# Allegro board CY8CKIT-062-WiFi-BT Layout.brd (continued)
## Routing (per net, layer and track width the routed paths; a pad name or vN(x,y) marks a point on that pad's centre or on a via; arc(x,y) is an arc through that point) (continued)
P8_1: length 24.6
  TOP w0.203: U1.H12 v2(82.2,36.95) ; R61.2 v1(90.53,19.15)
  L06_SIG w0.203: v1(90.53,19.15) 87.22,22.45 87.22,29.3 82.78,33.75 82.78,36.37 v2(82.2,36.95)
  BOTTOM w0.203: R61.2 v1(90.53,19.15)
P8_2: length 23.4
  TOP w0.203: U1.H11 v2(82.2,37.6) ; R60.2 v1(90.53,21.06)
  L06_SIG w0.114: v2(82.2,37.6) 83.21,36.59 83.21,35.28
  L06_SIG w0.203: v1(90.53,21.06) 87.99,23.59 87.99,29.52 83.21,34.31 83.21,35.28
  BOTTOM w0.203: R60.2 v1(90.53,21.06)
P8_3: length 18.4
  TOP w0.203: v2(84.16,35.69) 83.68,35.69 83.13,36.24 U1.G13 ; R53.2 90.62,26.77 v1(90.53,26.87)
  L06_SIG w0.203: v2(84.16,35.69) 84.3,35.55 88.27,35.55 90.13,33.69 90.13,27.26 v1(90.53,26.87)
  BOTTOM w0.203: R53.2 90.75,26.77 90.65,26.87 v1(90.53,26.87)
P8_4: length 17.3
  TOP w0.203: R52.2 v1(90.99,28.68) ; U1.G12 v2(83.42,36.95)
  L06_SIG w0.114: 84.4,36.68 84.4,37.06 84.39,37.06 84.39,37.09 84.2,37.28 83.74,37.28 v2(83.42,36.95)
  L06_SIG w0.203: v1(90.99,28.68) 90.84,28.83 90.84,34.22 89.08,35.98 84.81,35.98 84.4,36.4 84.4,36.68
  BOTTOM w0.203: R52.2 v1(90.99,28.68)
P8_5: length 16.6
  TOP w0.203: v1(91.68,31.63) 92.01,31.29 R47.2 ; U1.G11 v2(83.42,37.6)
  L06_SIG w0.114: v2(83.42,37.6) 84.22,37.6 84.55,37.28 84.94,37.28 85.05,37.17 85.05,36.66 85.06,36.64
  L06_SIG w0.203: 85.06,36.64 85.14,36.57 90.6,36.57 92.36,34.81 92.36,32.31 v1(91.68,31.63)
  BOTTOM w0.203: v1(91.68,31.63) 91.68,30.92 R47.2
P8_6: length 19.4
  TOP w0.203: U1.F13 83.78,36.29 v2(83.92,36.15) ; v1(90.53,24.83) 90.56,24.87 R58.2
  L06_SIG w0.114: 84.73,35.13 84.26,35.13 83.83,35.56 83.83,36.06 v2(83.92,36.15)
  L06_SIG w0.203: v1(90.53,24.83) 89.42,25.94 89.42,33 87.29,35.13 84.73,35.13
  BOTTOM w0.203: R58.2 90.56,24.87 v1(90.53,24.83)
P8_7: length 21.2
  TOP w0.203: v1(90.53,23.06) 90.62,22.96 R59.2 ; U1.F12 v2(84.07,36.95)
  L06_SIG w0.114: v2(84.07,36.95) 83.6,36.48 83.6,35.15 84.21,34.54
  L06_SIG w0.203: 84.21,34.54 85.5,34.54 88.7,31.33 88.7,24.88 v1(90.53,23.06)
  BOTTOM w0.203: v1(90.53,23.06) 90.56,23.06 90.65,22.96 R59.2
P9_0: length 47.7
  TOP w0.114: U1.E11 v2(84.72,37.6)
  L06_SIG w0.114: v1(51.54,21.4) 52.72,22.59 59.99,22.59 60.15,22.76 66.19,22.76 v1(67.03,21.91)
  BOTTOM w0.114: J2.2 50.24,20.11 v1(51.54,21.4) ; v2(84.72,37.6) 84.39,37.28 83.29,37.28 81.79,35.78 81.79,33.06 77.83,29.1 77.83,24.99 74.75,21.91 v1(67.03,21.91)
P9_1: length 44.8
  TOP w0.114: U1.E12 v2(84.72,36.95)
  L06_SIG w0.114: v1(65.53,21.96) 64.92,21.35 61.82,21.35 61.65,21.53 53.57,21.53 v1(53.31,21.28)
  BOTTOM w0.114: v2(84.72,36.95) 84.4,36.63 83.95,36.63 83.24,35.92 83.24,34.96 82.3,34.01 82.3,32.91 78.21,28.82 78.21,24.83 74.65,21.28 66.22,21.28 v1(65.53,21.96) ; v1(53.31,21.28) 52.81,20.77 52.81,19.3 J2.4
P9_2: length 44
  TOP w0.114: v1(81.49,23.04) 81.31,23.23 81.31,31.29 84.53,34.51 84.53,36.49 U1.E13
  L06_SIG w0.114: v1(58.39,23.06) 67.03,23.06 67.54,22.55 76.78,22.55 77.32,23.08 81.45,23.08 v1(81.49,23.04)
  BOTTOM w0.114: J2.6 55.32,20.74 57.63,23.06 v1(58.39,23.06)
P9_3: length 35.4
  TOP w0.114: U1.F11 v2(83.78,38.25)
  L03_SIG w0.114: v1(61.19,24.83) 61.06,24.96 61.06,29.96 62.53,31.44 63.17,31.44 v1(63.22,31.49)
  L06_SIG w0.114: v2(83.78,38.25) 82.85,38.25 82.61,38 82.05,38 81.87,37.82 81.87,36.76 80.48,35.36 78.93,35.36 78.11,34.54 66.27,34.54 v1(63.22,31.49)
  BOTTOM w0.114: v1(61.19,24.83) 61.08,24.72 R161.1 R162.1
P9_4: length 38.6
  TOP w0.114: v1(81.36,21.91) 82,22.55 82,23.96 81.61,24.34 81.61,31.19 85.08,34.67 U1.D13
  L06_SIG w0.114: J2.10 62.1,20.97 80.42,20.97 v1(81.36,21.91)
P9_5: length 35.7
  TOP w0.114: U1.D12 v2(85.37,36.95)
  BOTTOM w0.114: J2.12 64.22,18 74.04,18 74.73,18.69 74.73,20.08 79.1,24.45 79.1,28.59 83.55,33.05 83.55,34.01 85.37,35.83 v2(85.37,36.95)
P9_6: length 29
  TOP w0.114: U1.D11 v2(85.37,37.6)
  BOTTOM w0.114: v2(85.37,37.6) 85.04,37.28 85.04,36.08 82.98,34.01 82.98,33.04 78.6,28.66 78.6,24.6 74.78,20.77 69.51,20.77 J2.16
P9_7: length 29.5
  TOP w0.114: v1(81.41,20.62) 82.25,21.46 82.25,24.24 81.86,24.63 81.86,31.04 85.73,34.91 U1.C13
  L06_SIG w0.114: v1(81.41,20.62) 81.28,20.49 71.77,20.49 J2.18
P10_0: length 53.2
  TOP w0.114: U1.C12 v2(86.02,36.95)
  L06_SIG w0.114: J2.1 52.55,14.43 69.18,14.43 70.21,13.4 71.75,13.4 v1(72.26,13.91)
  BOTTOM w0.114: v1(72.26,13.91) 73.03,14.67 73.84,14.67 75.39,16.22 75.39,19.47 79.86,23.94 79.86,28.24 84.87,33.25 84.87,34.01 86.02,35.16 v2(86.02,36.95)
P10_1: length 54.7
  TOP w0.114: U1.A11 87.33,37.89 v2(87.66,38.21)
  L03_SIG w0.114: v1(79.04,15.11) 80.19,16.25 80.19,29.13 87.66,36.6 v2(87.66,38.21)
  L06_SIG w0.114: J2.3 54.79,14.73 76.97,14.73 77.34,15.11 v1(79.04,15.11)
P10_2: length 50.2
  TOP w0.114: U1.B11 v2(86.67,37.6) ; J2.5 57.49,14.57 68.78,14.57 70.33,13.02 72.69,13.02 v1(73.53,13.86)
  BOTTOM w0.114: v1(73.53,13.86) 74.37,13.86 75.72,15.21 75.72,19.17 80.24,23.69 80.24,28.01 85.28,33.05 85.28,34.01 86.35,35.08 86.35,37.28 v2(86.67,37.6)
P10_3: length 45.3
  TOP w0.114: v1(70.56,13.94) 69.8,13.94 68.78,14.95 59.65,14.95 J2.7 ; U1.C11 v2(86.02,37.6)
  BOTTOM w0.114: v1(70.56,13.94) 71.68,15.05 73.38,15.05 75.01,16.68 75.01,19.7 79.48,24.17 79.48,28.41 84.19,33.13 84.19,34.01 85.69,35.51 85.69,37.28 v2(86.02,37.6)
P10_4: length 52.9
  TOP w0.114: U1.A10 87.18,38.68 87.98,38.68 88.27,38.39 v2(88.27,37.61)
  L03_SIG w0.114: v1(78.99,13.35) 80.47,14.83 80.47,29.01 88.27,36.81 v2(88.27,37.61)
  L06_SIG w0.114: v1(78.99,13.35) 79.53,13.89 79.53,15.44 79.17,15.79 76.43,15.79 75.73,15.09 62.05,15.09 J2.9
P10_5: length 45.1
  TOP w0.114: U1.B10 v2(86.67,38.25)
  BOTTOM w0.114: J2.11 64.63,15.05 67.36,15.05 69.52,12.9 75.6,12.9 77.47,14.77 77.47,19.78 81.08,23.39 81.08,27.73 86.06,32.71 86.06,33.49 87.22,34.66 87.22,37.83 86.8,38.25 v2(86.67,38.25)
P10_6: length 42.2
  TOP w0.114: U1.C10 v2(86.02,38.25)
  BOTTOM w0.114: J2.13 66.78,15.44 67.79,15.44 69.95,13.28 75.44,13.28 77.14,14.98 77.14,20.03 80.62,23.51 80.62,27.83 85.67,32.89 85.67,33.7 86.99,35.02 86.99,37.74 86.8,37.93 86.34,37.93 v2(86.02,38.25)
P10_7: length 63.2
  TOP w0.114: v1(88.94,38.74) 88.49,39.19 U1.A9
  L03_SIG w0.114: v1(94.31,66.6) 95.52,66.6 98.6,63.52 98.6,58.41 95.17,54.98 95.17,48.07 92.99,45.88 92.99,44.83 89.61,41.49 88.95,40.84 88.94,40.78 88.94,40.65 88.94,40.65 v1(88.94,38.74)
  L06_SIG w0.114: v1(94.31,66.6) 94.04,66.87 86.84,66.87 85.07,68.65 84.94,68.65 84.93,68.65 81.41,68.65 78.19,65.43 74.55,65.43 73.74,66.24 71.8,66.24 J21.5
P11_0: length 32.1
  TOP w0.114: U1.B9 v2(86.67,38.9)
  L03_SIG w0.114: v1(79.04,17.72) 79.65,18.33 79.65,29.41 86.35,36.1 86.35,38.58 v2(86.67,38.9)
  BOTTOM w0.114: R175.1 84.05,16.83 83.03,17.85 81.89,17.85 81.37,17.33 R173.1 79.44,17.33 v1(79.04,17.72)
P11_1: length 40.4
  TOP w0.114: v1(118.97,44.04) 118.97,45.83 118.58,46.22 R19.2 ; U1.C9 v2(86.02,38.9)
  L06_SIG w0.114: v1(118.97,44.04) 118.15,43.21 118.15,41.92 114.78,38.55 93.32,38.55 92.65,37.88 88.76,37.88 88.06,38.58 86.34,38.58 v2(86.02,38.9)
P11_2: length 32.8
  TOP w0.114: v2(88,39.97) 87.87,39.84 U1.A8
  L03_SIG w0.114: v2(88,39.97) 87.07,39.04 87.07,36.42 79.91,29.26 79.91,17.34 v1(78.97,16.4)
  BOTTOM w0.114: R176.1 82.27,13.54 R177.1 80.48,15.32 79.4,16.4 v1(78.97,16.4)
P11_3: length 34.6
  TOP w0.114: v1(105.23,41.37) 105.23,47.6 R17.1 ; U1.B8 v2(86.67,39.55) ; U4.D4 112.34,42.14 v1(111.2,42.14)
  L06_SIG w0.114: v1(105.23,41.37) 104.45,40.58 90.53,40.58 89.5,39.55 v2(86.67,39.55)
  BOTTOM w0.114: v1(111.2,42.14) 108.54,42.14 108,41.6 107.15,41.6 106.77,41.98 105.84,41.98 v1(105.23,41.37)
P11_4: length 34.4
  TOP w0.114: U5.3 106.5,39.96 v1(106.49,39.97) 106.01,40.45 102.59,40.45 R38.1 ; U1.C8 v2(86.02,39.55) ; U4.C4 112.36,40.11 v1(111.02,40.11)
  L06_SIG w0.114: v1(106.49,39.97) 105.53,39.01 89.83,39.01 89.61,39.23 86.34,39.23 v2(86.02,39.55)
  BOTTOM w0.114: v1(106.49,39.97) 106.63,40.11 v1(111.02,40.11)
P11_5: length 32.3
  TOP w0.114: v1(94.34,39.95) 93.79,40.49 U1.A7 ; 105.23,38.31 v1(105.23,39.82) ; U4.D2 v1(115.26,42.01)
  L06_SIG w0.114: v1(115.26,42.01) 114.48,41.22 110.08,41.22 109.5,41.8 107.97,41.8 107.96,41.8 107.58,41.8 107.58,41.8 107.56,41.8 105.86,40.1 105.51,40.1 v1(105.23,39.82) 104.8,39.39 94.89,39.39 v1(94.34,39.95)
P11_6: length 32.6
  TOP w0.114: U5.5 v1(107.77,42.26) ; U1.B7 v2(86.67,40.2) ; U4.D3 v1(113.48,42.01)
  L06_SIG w0.114: v1(107.77,42.26) 104.65,42.26 103.74,41.35 89.92,41.35 89.25,40.68 87.68,40.68 87.2,40.2 v2(86.67,40.2)
  BOTTOM w0.114: v1(113.48,42.01) 112.37,42.01 111.63,42.74 108.25,42.74 v1(107.77,42.26)
P11_7: length 35.6
  TOP w0.114: v1(106.55,41.45) 106.5,41.5 U5.6 ; U4.B2 v1(114.48,40.01) ; U1.C7 v2(86.02,40.2)
  L06_SIG w0.114: v1(106.55,41.45) 105.99,41.45 105.56,41.88 104.83,41.88 103.91,40.97 90.28,40.97 89.61,40.29 87.72,40.29 87.31,39.88 86.34,39.88 v2(86.02,40.2)
  BOTTOM w0.114: v1(106.55,41.45) 107.24,40.76 109.65,40.76 109.86,40.96 113.52,40.96 v1(114.48,40.01)
P12_0: length 180.1
  TOP w0.114: U1.A6 87.53,41.14 v2(88.01,41.62)
  L03_SIG w0.114: J5.4 66.83,43.48 66.83,46.19 65.38,47.64 65.38,55.8 v1(66.65,57.07) ; J3.4 31.84,63.37 30.61,63.37 25.43,58.18 25.43,49.29 23.67,47.54 23.67,30.45 22.78,29.56 22.78,12.06 30.19,4.65 J14.2 ; v1(92.18,61.92) 92.18,61.41 94.6,58.99 94.6,55.93 94.34,55.67 94.34,48.68 92.08,46.42 92.08,45.14 88.56,41.62 v2(88.01,41.62)
  L06_SIG w0.114: J3.4 35.11,63.37 36.86,63.37 38.73,61.49 50.97,61.49 54.91,57.55 61.52,57.55 v1(62.46,58.49) 63.88,57.07 v1(66.65,57.07) 66.65,57.6 68.32,59.28 73.56,59.28 74.93,60.65 78.97,60.65 82.27,63.95 84.43,63.95 85.95,62.43 91.67,62.43 v1(92.18,61.92)
  BOTTOM w0.114: R77.1 v1(62.46,58.49)
P12_1: length 153.8
  TOP w0.114: U1.B6 v2(86.67,40.85)
  L03_SIG w0.114: v1(63.58,53.48) 63.8,53.26 63.8,46.7 62.94,45.84 J5.1 ; J3.5 30.94,64.05 25.04,58.16 25.04,49.32 23.42,47.69 23.42,30.57 22.53,29.68 22.53,11.8 27.65,6.68 J14.3
  L06_SIG w0.114: v1(63.58,53.48) 63.58,54.07 v1(62.59,55.06) 63.09,55.57 63.09,57.35 62.84,57.6 62.08,57.6 61.59,57.12 54.86,57.12 50.74,61.24 34.7,61.24 J3.5
  BOTTOM w0.114: v1(62.59,55.06) 61.58,55.06 R85.1 ; J5.1 61.52,43.26 61.52,39.29 62.43,38.38 64.48,38.38 65.46,37.41 76.68,37.41 77.2,37.93 85.5,37.93 85.69,38.12 85.69,38.39 85.89,38.58 86.8,38.58 87,38.77 87,40.53 v2(86.67,40.85)
P12_2: length 152.3
  TOP w0.114: U1.C6 v2(86.02,40.85)
  L03_SIG w0.114: v1(62.59,56.96) 62,56.96 61.67,56.63 61.67,54.6 63.42,52.85 63.42,46.96 61.8,45.33 61.8,43.28 J5.3 ; J14.4 25.11,8.59 22.28,11.42 22.28,29.89 23.11,30.73 23.11,45 21.41,46.7 21.41,56.08 28.4,63.06 J3.6
  L06_SIG w0.114: v1(62.59,56.96) 62.18,56.56 54.81,56.56 51.54,59.83 33.56,59.83 J3.6
  BOTTOM w0.114: v1(62.59,56.96) 61.58,56.96 R81.1 ; v2(86.02,40.85) 86.34,40.53 86.34,39.42 86.16,39.23 85.89,39.23 85.69,39.04 85.69,39.02 85.26,38.58 77.02,38.58 76.35,37.91 65.55,37.91 64.31,39.16 64.31,40.77 J5.3
P12_3: length 87.9
  TOP w0.114: v1(93.38,63.64) 93.38,60.39 94.62,59.15 94.62,59.13 94.63,59.12 94.63,56.23 94.62,56.22 94.62,56.21 91.41,53.01 91.41,48.46 90.19,47.23 90.19,45.75 87.54,43.1 87.54,42.3 U1.A5
  L06_SIG w0.114: v1(93.38,63.64) 92.66,62.93 86.33,62.93 84.56,64.71 82.02,64.71 78.46,61.16 74.65,61.16 73.56,60.06 65.48,60.06 63.77,61.77 39.24,61.77 J3.3
P12_4: length 69.4
  TOP w0.114: U1.B5 v2(86.67,41.5) ; v1(63.73,58.62) 64.21,58.13 66.67,58.13 69.09,60.55 71.25,60.55 72.35,61.65 76.8,61.65 81.8,66.65 91.62,66.65 v1(92.08,66.19)
  L03_SIG w0.114: v2(86.67,41.5) 87.19,41.5 87.48,41.22 88.51,41.22 92.41,45.11 92.41,46.26 94.64,48.5 94.64,55.29 97.83,58.48 97.83,63.15 95.38,65.6 93.31,65.6 92.72,66.19 v1(92.08,66.19)
  BOTTOM w0.114: R74.1 v1(63.73,58.62) R83.1
P12_5: length 69.4
  TOP w0.114: v1(93.29,66.28) 92.66,66.92 81.68,66.92 76.72,61.96 72.3,61.96 71.2,60.85 68.76,60.85 66.52,58.62 v1(65.38,58.62) ; U1.C5 v2(86.02,41.5)
  L03_SIG w0.114: v2(86.02,41.5) 86.35,41.18 87.06,41.18 87.25,40.99 88.72,40.99 92.71,44.97 92.71,46.09 94.89,48.27 94.89,55.06 98.25,58.41 98.25,63.37 95.57,66.05 93.53,66.05 v1(93.29,66.28)
  BOTTOM w0.114: R82.1 v1(65.38,58.62) R73.1
P12_6: length 5.4
  TOP w0.114: U1.A4 v2(86.75,42.15)
  BOTTOM w0.114: v2(86.75,42.15) 88.52,42.15 89.04,41.63 R131.1 R135.1
P12_7: length 6.3
  TOP w0.114: U1.B4 v2(86.1,42.15)
  BOTTOM w0.114: v2(86.1,42.15) 86.47,42.52 88.37,42.52 89.14,43.28 R126.1 R120.1
P13_0: length 75.5
  TOP w0.114: v2(86.69,44.93) 86.69,44.69 U1.B1
  L03_SIG w0.114: 86.69,46.19 v2(86.69,44.93)
  L03_SIG w0.203: v1(88.49,65.47) 89.28,65.47 89.89,64.86 89.89,61.89 91.18,60.61 91.18,54.68 88.87,52.38 88.87,50.61 87.73,49.47 87.73,47.24 86.69,46.19
  L06_SIG w0.114: v1(88.49,65.47) 87.98,64.96 86.57,64.96 85.12,66.41 81.25,66.41 77.75,62.91 67.28,62.91 66.93,62.55 64.72,62.55 64.36,62.91 43.19,62.91 J3.1
P13_1: length 83
  TOP w0.114: U1.A3 89.81,45.87 89.81,47.36 91.16,48.71 91.16,53.1 94.39,56.33 94.39,59.02 93.09,60.32 93.09,62.81 v1(92.28,63.62)
  L06_SIG w0.114: J3.2 41.54,62.02 64.21,62.02 65.79,60.44 73.55,60.44 74.51,61.41 78.21,61.41 81.89,65.09 84.68,65.09 86.59,63.18 91.84,63.18 v1(92.28,63.62)
P13_2: length 62.8
  TOP w0.114: U1.B3 v2(86.67,43.37)
  L03_SIG w0.114: v2(86.67,43.37) 86.35,43.7 86.35,45.28
  L03_SIG w0.178: v1(89,64.71) 89,62.81
  L03_SIG w0.203: 89,62.81 86.72,60.52 86.72,56.84 86.08,56.2 86.08,53.64 87.58,52.14 87.58,51.29 87.1,50.81 87.1,47.48 86.05,46.42 86.05,45.57 86.33,45.28 86.35,45.28
  L06_SIG w0.203: J21.2 65.49,67.54 66.75,66.28 66.75,64.12 67.16,63.71 77.26,63.71 81.66,68.12 84.81,68.12 86.69,66.24 89.26,66.24 89.64,65.85 89.64,65.35 v1(89,64.71)
  BOTTOM w0.178: R72.2 67.92,62.96 66.77,64.11 66.77,66.25 J21.2
P13_3: length 58.2
  TOP w0.203: U1.B2 v2(86.67,44.02)
  L03_SIG w0.203: v2(86.67,44.02) 87.27,44.63 87.27,45.84 89.49,48.05 89.49,51.99 92.68,55.19 93.09,55.19 94.06,56.15 94.06,58.64 90.65,62.04 v1(90.65,64.71)
  L06_SIG w0.203: v1(70.58,61.65) 71.28,62.36 77.99,62.36 81.44,65.81 84.85,65.81 86.61,64.06 90,64.06 v1(90.65,64.71)
  BOTTOM w0.178: J21.4 68.03,67.54 69.31,66.26 69.31,60.89 69.55,60.65 R71.1 v1(70.58,61.65)
P13_4: length 33.8
  TOP w0.114: U1.C2 v2(86.02,44.02)
  L03_SIG w0.114: v2(86.02,44.02) 86.02,44.2 83.83,46.39 83.83,46.96
  L03_SIG w0.178: v1(80.87,58.41) 81.76,57.52 81.76,56.58 81.38,56.2 81.38,51.63 83.83,49.18 83.83,46.96
  BOTTOM w0.178: v1(80.87,58.41) 80.25,59.03 77.28,59.03 76.94,59.38 74.52,59.38 74.13,59.77 R70.1 74.13,61.55 71.85,63.83 71.85,66.26 70.57,67.54 J21.6
P13_5: length 41.6
  TOP w0.114: U1.C1 v2(86.02,44.67)
  L03_SIG w0.114: v1(86.97,67.51) 87.48,67 87.48,62.68 83.41,58.62 83.41,56.05 84.3,55.16 84.3,52.8 85.57,51.53 85.57,49.57 85.83,49.32 85.83,48.96 85.45,48.58 85.45,45.25 v2(86.02,44.67)
  L06_SIG w0.114: J21.8 73.1,67.55 74.48,68.92 85.55,68.92 v1(86.97,67.51)
P13_6: length 91.1
  TOP w0.114: U1.D3 v2(85.37,43.37)
  L03_SIG w0.114: v1(78.97,18.97) 79.4,19.4 79.4,29.57 85.69,35.86 85.69,39.93 85.12,40.5 85.12,42.65 85.37,42.89 v2(85.37,43.37)
  L06_SIG w0.114: v2(85.37,43.37) 85.69,43.7 86.8,43.7 87.13,43.38 88.6,43.38 89,43.78 100.18,43.78 101.27,44.87 111.78,44.87 113.36,46.46 114.03,46.46 116.41,48.84 119.2,48.84 120.52,47.52 120.52,46.57 120.85,46.24 120.85,45.15 121.11,44.9 123.01,44.9 128.73,39.18 132.61,39.18 132.72,39.08 v1(132.72,39.06) ; J2.19 76.74,16.74 v1(78.97,18.97)
  BOTTOM w0.114: v1(132.72,39.06) 133.1,38.68 R45.2
P13_7: length 88.1
  TOP w0.114: U1.D2 v2(85.37,44.02) ; v1(125.73,42.99) 125.68,43.05 R31.1
  L03_SIG w0.114: v2(85.37,44.02) 85.05,43.7 85.05,43.26 85.04,43.25 85.04,43.1 84.47,42.53 84.47,41.58 84.71,41.34 84.71,38.73 85.04,38.39 85.04,35.63 79.15,29.74 79.15,20.24 v1(78.92,20.01) ; v1(125.32,49.09) 125.2,48.96 125.2,43.53 v1(125.73,42.99)
  L06_SIG w0.114: v1(125.32,49.09) 125.12,49.09 121.43,52.78 116.19,52.78 115.34,51.94 108.74,51.94 107.16,50.36 100.94,50.36 99.8,49.22 v1(96.4,49.22) ; J2.20 73.83,20.01 v1(78.92,20.01)
  BOTTOM w0.114: v1(96.4,49.22) 96.19,49.01 95.14,49.01 93.62,47.49 93.62,46.27 93.27,45.92 89.13,45.92 88.75,46.3 87.99,46.3 87.73,46.04 87.73,44.9 86.99,44.16 86.99,43.89 86.8,43.7 86.79,43.7 86.78,43.7 85.7,43.7 v2(85.37,44.02)
PMIC_EN: length 89.7
  TOP w0.114: v1(96.88,58.74) 96.88,56.43 98.25,55.06 98.25,51.42 v1(99.71,49.95) ; U9.3 64.78,34.42 65.28,34.92 v1(65.43,34.92) ; v1(66.4,27.5) 65.89,27.5 65.44,27.05 U10.3
  L03_SIG w0.114: v1(59.39,46.05) 59.39,41.98 60.03,41.33 60.03,41.08 60.64,40.48 60.64,36.94 61.47,36.11 65.13,36.11 65.48,35.76 65.48,34.97 v1(65.43,34.92) 64.62,34.1 64.62,29.28 v1(66.4,27.5)
  L06_SIG w0.114: v1(66.32,53.84) 68.45,55.97 68.45,58.26 69.09,58.89 73.63,58.89 75.13,60.39 79.1,60.39 82.35,63.65 84.37,63.65 85.85,62.17 91.16,62.17 94.59,58.74 v1(96.88,58.74)
  BOTTOM w0.114: v1(66.32,53.84) 66.32,51.97 60.41,46.05 v1(59.39,46.05) ; SW7.6 99.92,51.12 99.71,50.91 v1(99.71,49.95)
PMOD_SSEL_P12_5: length 103.1
  TOP w0.114: v1(26.46,58.51) 27.84,59.89 48.36,59.89 51.79,56.46 61.06,56.46 61.57,55.95 66.31,55.95 v1(66.35,55.9)
  L03_SIG w0.114: v1(26.46,58.51) 27.08,57.89 27.08,38.85 25.63,37.41 25.63,29.02 25.1,28.49 25.1,23.03 24.79,22.73 24.79,10.96 J14.1
  BOTTOM w0.114: R82.2 65.44,55.87 66.32,55.87 v1(66.35,55.9)
SDIO_CLK: length 5.4
  TOP w0.114: v1(125.12,50.54) 125.37,50.79 U6.20
  BOTTOM w0.114: R108.2 124.94,47.32 124.94,48.6 124.82,48.73 124.82,50.23 v1(125.12,50.54)
SDIO_CMD: length 4.1
  TOP w0.114: v1(126.07,50.06) 126.42,50.4 126.42,51.7 126.07,52.05 U6.22
  BOTTOM w0.114: R99.2 126.73,50.72 v1(126.07,50.06)
SDIO_DATA0: length 8
  TOP w0.114: U6.24 126.27,52.95 127.18,52.04 127.18,52.02 127.18,52.02 127.18,50.81 v1(128.17,49.83)
  BOTTOM w0.114: R110.2 127.82,47.21 127.82,49.48 v1(128.17,49.83)
SDIO_DATA1: length 10.3
  TOP w0.114: v1(130.51,49.62) 129.67,50.46 128.93,50.46 127.96,51.44 127.96,52.17 126.28,53.85 U6.26
  BOTTOM w0.114: v1(130.51,49.62) 130.81,49.32 130.81,47.21 R111.2
SDIO_DATA2: length 7.3
  TOP w0.114: U6.23 126.18,52.5 126.8,51.88 126.8,51.86 126.8,51.86 126.8,50.18 v1(127.11,49.87)
  BOTTOM w0.114: v1(127.11,49.87) 127.11,49.84 126.72,49.45 126.72,48.84 126.57,48.68 126.57,47.45 125.68,46.57 R112.2
SDIO_DATA3: length 9
  TOP w0.114: v1(129.34,49.8) 128.98,49.8 127.56,51.22 127.56,52.09 126.26,53.4 U6.25
  BOTTOM w0.114: R109.2 129.34,47.23 v1(129.34,49.8)
SHIELD: length 60.4
  TOP w0.381: 117.86,11.15 v1(117.86,11.63) ; v1(117.86,11.63) 117.86,12.77 ; v1(117.86,11.63) 117.13,11.63 ; v1(117.86,11.63) 118.33,11.63 ; v1(132.21,16.32) 132.21,17.1 ; v1(132.21,16.32) 132.21,16.16 ; v1(132.21,16.32) 131.11,16.32 ; v1(132.21,16.32) 132.37,16.32 ; 132.64,24.14 v1(132.64,24.66) ; v1(132.64,24.66) 133.23,24.66 ; v1(132.64,24.66) 132.12,24.66 ; v1(132.64,24.66) 132.64,25.93 ; 116.81,2.61 v1(118.52,2.61) ; v1(118.52,2.61) 118.52,2.47 ; v1(118.52,2.61) 118.66,2.61 ; v1(118.52,2.61) 118.52,2.77 ; 113.28,6.57 v1(114.53,6.57) ; v1(114.53,6.57) 114.72,6.57 ; v1(114.53,6.57) 114.53,5.95 ; v1(114.53,6.57) 114.53,6.76 ; v1(99.26,30.19) 99.54,30.19 ; v1(99.26,30.19) 99.26,31.36 ; v1(99.26,30.19) 99.26,29.91 ; v1(99.26,30.19) 98.57,30.19 ; v1(100.66,20.46) 100.66,20.63 ; v1(100.66,20.46) 100.66,20.1 ; v1(100.66,20.46) 100.82,20.46 ; v1(100.66,20.46) 99.16,20.46 ; v1(99.26,2.38) 99.26,3.35 ; v1(99.26,2.38) 99.26,1.89 ; v1(99.26,2.38) 99.75,2.38 ; 101.07,16.48 v1(102.03,16.48) ; v1(102.03,16.48) 102.64,16.48 ; v1(102.03,16.48) 102.03,15.87
  BOTTOM w0.381: 130.93,24.66 v1(132.64,24.66) ; v1(132.64,24.66) 132.64,25.22 ; v1(132.64,24.66) 133.2,24.66 ; v1(132.64,24.66) 132.64,23.59 ; 99.26,1.28 v1(99.26,2.38) ; v1(99.26,2.38) 99.26,3.27 ; v1(99.26,2.38) 100.16,2.38 ; v1(99.26,30.19) 99.26,30.93 ; v1(99.26,30.19) 100,30.19 ; v1(99.26,30.19) 99.26,28.94 ; v1(102.03,16.48) 102.03,17.1 ; v1(102.03,16.48) 102.03,15.12 ; v1(102.03,16.48) 102.66,16.48 ; v1(102.03,16.48) 100.63,16.48 ; 117.18,2.61 v1(118.52,2.61) ; v1(118.52,2.61) 118.52,1.17 ; v1(118.52,2.61) 118.52,3.38 ; v1(118.52,2.61) 119.29,2.61 ; 130.9,16.32 v1(132.21,16.32) ; v1(132.21,16.32) 132.21,17.35 ; v1(132.21,16.32) 133.23,16.32 ; v1(132.21,16.32) 132.21,14.87 ; v1(114.53,6.57) 114.53,7.37 ; v1(114.53,6.57) 114.53,5.48 ; v1(114.53,6.57) 115.33,6.57 ; v1(114.53,6.57) 112.85,6.57 ; 100.66,19.28 v1(100.66,20.46) ; v1(100.66,20.46) 100.66,21.24 ; v1(100.66,20.46) 99.08,20.46 ; v1(100.66,20.46) 101.43,20.46 ; R44.1 R45.1 133.1,34.01 R145.1 133.03,33 133.38,32.66 134.58,32.66 134.85,32.39 134.85,31.36 134.87,31.34 v1(134.81,31.28)
SPI_MISO: length 79.3
  TOP w0.114: v1(45.67,33.11) 45.67,32.61 45.35,32.29 U2.4 ; v1(53.67,54.71) 53.18,54.22 52.25,54.22 50.74,55.73 v1(48.17,55.73)
  L03_SIG w0.114: v1(45.67,33.11) 46.33,33.77 46.33,44.82 47.83,46.33 47.83,52.19 48.17,52.53 v1(48.17,55.73)
  L06_SIG w0.114: J6.9 3.66,28.81 5.68,28.81 6.22,28.26 25.72,28.26 28.11,30.66 34.47,30.66 36.43,32.61 45.17,32.61 v1(45.67,33.11)
  BOTTOM w0.114: v1(53.67,54.71) 53.91,54.95 U17.17
SPI_MOSI: length 86.2
  TOP w0.114: U2.28 39.84,39.91 38.68,41.06 38.68,42.59 37.14,44.14 v1(30.48,44.14) 29.87,43.53 29.87,41.45 26.04,37.61 7.16,37.61 5.77,39.01 3.44,39.01 J6.3 ; v1(32.37,57.1) 34.88,59.61 48.01,59.61 52.24,55.38 53.19,55.38 v1(53.67,55.85)
  L03_SIG w0.114: v1(30.48,44.14) 32.37,46.03 v1(32.37,57.1)
  BOTTOM w0.114: U17.19 53.77,55.95 v1(53.67,55.85)
SPI_SCLK: length 81.5
  TOP w0.114: J6.5 3.43,34.12 17.52,34.12 18.5,35.1 25.35,35.1 26.09,35.83 28.14,35.83 v1(28.57,35.4) ; v1(33.48,35.28) 33.69,35.49 U2.40
  L03_SIG w0.114: v1(31.66,54.72) 31.63,54.72 28.57,51.66 v1(28.57,35.4)
  L06_SIG w0.114: v1(52.53,55.85) 51.84,55.17 43.55,55.17 42.91,55.82 32.75,55.82 v1(31.66,54.72)
  BOTTOM w0.114: v1(28.57,35.4) 29.2,34.77 30.87,34.77 31.38,35.28 v1(33.48,35.28) ; v1(52.53,55.85) 53.09,55.3 53.9,55.3 54.06,55.45 U17.18
SPI_SSEL: length 86
  TOP w0.114: v1(33.48,34.14) 34.43,35.09 U2.41 ; J6.7 3.37,33.86 17.73,33.86 18.69,34.82 25.48,34.82 25.98,35.32 v1(27.43,35.32) ; v1(31.68,55.99) 32.05,55.99 35.31,59.26 47.72,59.26 52.27,54.71 v1(52.53,54.71)
  L03_SIG w0.114: v1(31.68,55.99) 27.76,52.08 27.76,38.14 27.43,37.81 v1(27.43,35.32)
  BOTTOM w0.114: v1(33.48,34.14) 32.9,34.71 31.75,34.71 31.32,34.28 28.85,34.28 27.81,35.32 v1(27.43,35.32) ; U17.16 54.2,54.45 53.9,54.15 53.09,54.15 v1(52.53,54.71)
SWD_RST_L: length 105.6
  TOP w0.114: J12.10 58.45,6.14 58.81,6.5 66.51,6.5 v1(66.85,6.16) 67.16,6.48 78.66,6.48 78.84,6.29 J11.10
  L03_SIG w0.114: v1(33.96,7.92) 33.76,8.12 33.76,15.44 J1.6 ; v1(66.85,6.16) 66.75,6.26 66.75,21.21 66.48,21.49 66.48,22.47 67.56,23.55 67.56,34.94 65.51,37 63.58,37 62.94,37.64 J5.5
  L06_SIG w0.114: J12.10 58.45,5.95 57.62,6.78 41.1,6.78 39.73,5.41 35.46,5.41 33.96,6.91 v1(33.96,7.92)
  BOTTOM w0.114: R182.1 79.44,7.28 78.84,6.68 J11.10 ; J12.10 58.45,6.62 R190.2
TCLK_SWCLK: length 30
  TOP w0.114: v1(75.26,7.51) 75.04,7.29 55.33,7.29 54.64,6.6 J12.4
  BOTTOM w0.114: R191.2 78.22,8.41 76.3,8.41 76.02,8.69 R183.1 75.92,8.17 v1(75.26,7.51) 75.03,7.28 J11.4
TMS_SWDIO: length 29
  TOP w0.114: J12.2 53.37,6.09 54.84,7.56 73.2,7.56 73.38,7.74 v1(74.02,7.74)
  BOTTOM w0.114: J11.2 73.76,6.55 74.02,6.8 v1(74.02,7.74) 72.81,7.74 R194.1 R192.2
TRACECLK: length 3.2
  BOTTOM w0.114: J12.12 59.72,7.08 R189.2
TRACEDATA_0: length 18.9
  L03_SIG w0.114: J12.14 60.99,9.97 61.73,10.72 61.73,21.44 v1(62.2,21.91)
  BOTTOM w0.114: v1(62.2,21.91) 61.95,21.66 R161.2
TRACEDATA_1: length 3.4
  BOTTOM w0.114: R188.2 62.26,6.72 J12.16
TRACEDATA_2: length 3.3
  BOTTOM w0.114: R187.2 63.53,6.97 J12.18
TRACEDATA_3: length 3.5
  BOTTOM w0.114: R186.2 64.8,6.52 J12.20
TS: length 8.8
  L06_SIG w0.114: TP7.1 53.41,50.9 v1(50.26,50.9)
  BOTTOM w0.114: U19.5 46.22,51.62 46.94,50.9 R95.1 R94.2 v1(50.26,50.9)
UART_CTS: length 88.4
  TOP w0.114: U2.61 41.04,29.65 41.15,29.54 41.15,28.36 v1(41.38,28.14)
  L03_SIG w0.114: v1(53.67,53.06) 55.22,51.51 55.22,51.5 55.44,51.29 55.44,46.77 v1(56.69,45.51) ; v1(41.38,28.14) 41.63,28.39 42.01,28.39 42.29,28.67 42.29,39.21 41.55,39.95 41.55,45.64 v1(40.84,46.35)
  L06_SIG w0.114: J6.2 6.03,41.6 7.17,41.6 8.44,40.33 16.41,40.33 18.08,42 20.4,42 20.7,41.7 23.85,41.7 28.5,46.35 v1(40.84,46.35) 41.38,46.88 44.22,46.88 44.91,46.19 56.01,46.19 v1(56.69,45.51)
  BOTTOM w0.114: v1(53.67,53.06) 54.06,53.45 U17.14
UART_RTS: length 83
  TOP w0.114: v1(52.43,53.47) 52.35,53.38 v1(51.33,53.38) ; v1(44.53,38.07) 44.31,38.29 U2.18
  L03_SIG w0.114: v1(44.53,38.07) 44.6,38 44.6,21.7 v1(41.82,18.92)
  L06_SIG w0.114: v1(41.82,18.92) 41.44,18.54 26.07,18.54 23.83,16.31 5.45,16.31 J7.7
  BOTTOM w0.114: v1(44.53,38.07) 45.31,38.85 47.83,38.85 48.72,39.74 48.72,43.68 51.33,46.3 v1(51.33,53.38) ; U17.15 54.24,53.95 54.06,53.77 52.74,53.77 v1(52.43,53.47)
UART_RX: length 72.3
  TOP w0.114: U2.21 42.64,39.99 42.75,40.11 v1(42.8,40.11)
  L03_SIG w0.114: v1(46.27,28.62) 46.25,28.64 46.25,30.93 47.32,32 v1(47.32,39.68)
  L06_SIG w0.114: J6.13 3.4,26.27 6.52,26.27 7.42,25.37 14.4,25.37 15.39,26.36 27.91,26.36 31.22,29.66 37.19,29.66 37.95,30.42 44.47,30.42 v1(46.27,28.62) ; v1(47.32,39.68) 46.82,39.18 43.18,39.18 42.7,39.67 42.7,40.01 v1(42.8,40.11)
  BOTTOM w0.114: J6.13 3.53,26.39 6.62,26.39 R156.1
UART_TX: length 59.7
  TOP w0.114: v1(43.76,40.11) 43.04,39.38 U2.20
  L03_SIG w0.114: v1(43.76,40.11) 43.76,37.76 44.17,37.36 44.17,30.35 43.51,29.69 43.51,26.61 v1(44.02,26.1)
  L06_SIG w0.114: v1(44.02,26.1) 43.11,25.2 33.32,25.2 32.07,26.44 29.67,26.44 28.68,25.44 16.65,25.44 15.71,24.5 8.6,24.5 v1(7.2,23.11)
  BOTTOM w0.114: J6.14 5.82,24.11 R159.1 v1(7.2,23.11)
USB_DEV_VBUS_DET: length 29
  L03_SIG w0.114: v1(77.6,59.81) 77.6,59.48 78.71,58.36 78.71,52.77 77.44,51.5 v1(77.44,49.6)
  BOTTOM w0.114: v1(77.44,49.6) 78.21,50.36 86.33,50.36 87.35,49.34 87.35,46.93 87.46,46.83 R107.1 88.73,46.83 88.91,46.65 U22.4 ; v1(77.6,59.81) 77.6,60.24 77.19,60.65 R70.2
USB_DM: length 18.1
  TOP w0.203: v1(80.43,49.45) 80.14,49.74 80.14,49.76 80.19,49.81 80.19,51.85 80.66,52.32 84.25,52.32 85.09,53.16 85.4,53.16 85.61,52.96 85.61,52.76 85.37,52.52 v1(85.24,52.52) ; U1.L1 v2(80.25,44.67)
  BOTTOM w0.152: 78.33,46.96 78.33,45.54 79.1,44.77 80.15,44.77 v2(80.25,44.67)
  BOTTOM w0.203: v1(85.24,52.52) 85.47,52.75 85.47,53.57 U16.2 ; v1(80.43,49.45) 80.01,49.03 80.01,48.39 79.45,47.83 79,47.83 78.33,47.16 78.33,46.96
USB_DP: length 20.2
  TOP w0.203: v1(86.21,52.39) 86,52.6 86,53.14 85.57,53.57 84.92,53.57 84.08,52.73 80.49,52.73 79.78,52.02 79.78,49.78 v1(79.45,49.45) ; U1.L2 v2(80.25,44.02)
  BOTTOM w0.152: 77.93,46.96 77.93,46.95 77.95,46.92 77.95,46.81 77.98,46.78 77.98,45.4 78.96,44.42 79.85,44.42 v2(80.25,44.02)
  BOTTOM w0.203: v1(86.21,52.39) 85.87,52.73 U16.1 ; v1(79.45,49.45) 79.6,49.29 79.6,48.56 79.28,48.23 78.84,48.23 77.93,47.33 77.93,46.96
USB_HOST_EN: length 30.1
  L06_SIG w0.114: v1(73.76,55.06) 73.76,55.19 74.4,55.82 74.78,55.82 77.57,53.03 81.13,53.03 81.64,52.52 84.05,52.52 84.94,53.41 87.35,53.41 v1(87.73,53.03)
  BOTTOM w0.114: R79.1 73.25,57.73 72.87,57.35 71.86,57.35 70.08,59.12 68.42,59.12 R72.1 ; v1(87.73,53.03) 88.11,52.65 R90.2 88.49,53.57 88.13,53.93 U16.10
  BOTTOM w0.152: R79.1 74,56.22 U14.2 74.02,55.31 v1(73.76,55.06)
USB_INT_L: length 13.4
  L03_SIG w0.114: v1(78.06,53.75) 73.58,58.23 v1(72.24,58.23)
  BOTTOM w0.152: v1(72.24,58.23) 72.38,58.37 R71.2 ; v1(78.06,53.75) 78.29,53.98 U15.3 79.61,53.98 79.73,53.86 R91.2
USB_TC_PWR_SENSE: length 37.8
  TOP w0.203: v1(19.76,45.44) 20.31,45.99 20.31,47.27 20.24,47.34 U3.39
  L03_SIG w0.203: v1(10.19,42.73) 10.5,42.42 11.76,42.42 12.78,41.4 12.78,31.09 10.52,28.83 10.52,27.24 10.73,27.03 10.87,27.03 v1(11.25,27.41)
  L06_SIG w0.203: v1(10.19,42.73) 10.52,42.39 14.1,42.39 15.11,43.41 19.11,43.41 20.22,44.52 20.22,44.98 v1(19.76,45.44)
  BOTTOM w0.203: R154.2 13.14,27.74 12.81,27.41 v1(11.25,27.41)
USB_V_SENSE: length 5
  TOP w0.114: U2.19 43.44,38.89 45.1,40.56 45.52,40.56 45.66,40.7 R37.2 R33.2
VBACKUP: length 146.4
  TOP w0.203: 85.29,45.19 85.29,44.6 U1.D1
  TOP w0.254: C25.1 84.8,45.68 85.29,45.19
  TOP w0.381: v1(106.78,52.27) v1(105.89,52.27) 103.73,52.27 100.38,48.91 98.88,48.91 96.75,51.05 96.75,52.95 97,53.21 97,54.53 v1(96.57,54.96) ; C25.1 C19.1
  L04_MIX w0.381: 97.51,46.17 97.51,33.47 97.15,33.1 81.91,33.1 78.08,29.28 78.08,12.51 77.7,12.13 77.7,8.83 v1(78.84,7.69)
  L05_MIX w0.381: v1(85.17,49.08) v1(84.45,49.08)
  L06_SIG w0.381: v1(78.84,7.69) 77.7,6.55 68.94,6.55 67.6,7.88 56.05,7.88 55.35,8.58 40.07,8.58 39.85,8.36 34.94,8.36 34.38,8.92 33.12,8.92 32.78,8.58 26.14,8.58 25.37,9.34 21.82,9.34 v1(20.75,8.27)
  BOTTOM w0.381: v1(96.57,54.96) 96.67,55.06 R86.2 97.32,54.64 96.81,54.14 U20.1 ; R66.1 17.26,9.15 18.14,8.27 v1(20.75,8.27) 20.75,7.36 R67.2
VBUCK1: length 4.8
  TOP w0.203: U1.K3 v2(81.47,42.8)
  BOTTOM w0.254: C98.1 79.43,42.8 v2(81.47,42.8) 81.63,42.65 R129.1
VDRV: length 53.8
  TOP w0.381: v1(48.49,60.39) 34.45,60.39 33.68,61.16 20.29,61.16 v1(20.04,60.9) ; v1(11.66,57.85) 11.75,57.76 LED6.A
  L03_SIG w0.381: v1(11.66,57.85) 15.35,61.55 19.39,61.55 v1(20.04,60.9) ; v1(48.59,51.92) 48.82,52.15 48.82,60.06 v1(48.49,60.39)
  BOTTOM w0.203: C73.1 47.6,53.19 47.03,52.62 U19.3
  BOTTOM w0.381: C73.1 47.72,51.94 R95.2 v1(48.59,51.92)
VREF: length 126.8
  TOP w0.203: C42.1 87.94,33.39 v1(87.52,33.82) 86.38,34.95 U1.B13
  TOP w0.381: v1(89.51,67.63) 94.82,67.63 99.03,63.42 99.03,57.22 100.43,55.82 100.43,53.07 v1(99.66,52.3)
  L03_SIG w0.381: v1(99.66,52.3) 99.51,52.46 99.46,52.51 99.44,52.52 98.88,53.08 97.38,53.08 96.99,52.69 96.99,44.41 90.91,38.32 90.91,37.2 v1(87.52,33.82)
  BOTTOM w0.381: v1(89.51,67.63) 87.6,69.54 43.92,69.54 43.15,68.78 43.15,63.82 42.65,63.31 25,63.31 J3.8
VRF: length 17.4
  TOP w0.254: C23.1 80.98,45.19 81.2,44.96 v1(81.2,44.93) 81.2,44.91 81.18,44.89 U1.K1
  L03_SIG w0.381: v1(81.2,44.93) 79.54,46.6 74.93,46.6 69.95,51.58 TP5.1
VTARG: length 3.2
  BOTTOM w0.381: 57.89,30.27 J8.2 ; J8.2 58.97,31.35 ; J8.2 57.89,32.43
  vias: v1(57.12,39.69) v1(58.01,39.69) v1(58.9,39.69) v1(75.51,45.19) v1(76.29,45.19) v1(83.49,51.56) v1(84.79,51.66) v1(86.03,51.61) v1(94.98,33.98) v1(95.06,34.7)
VTARG_BUF: length 40.6
  TOP w0.381: v1(73.13,50.11) 72.46,50.11 70.76,48.41 63.42,48.41 61.09,46.08 61.09,43.02 v1(59.16,41.09)
  BOTTOM w0.381: v1(59.16,41.09) 57.02,41.09 55.63,39.7 55.63,34.32 52.93,31.62 52.93,28.7 52.34,28.11 48.34,28.11
  vias: v1(73.13,50.87)
VTARG_IN: length 43.2
  TOP w0.381: R11.1 50.36,49.76 51.82,48.3 54.13,48.3 v1(54.18,48.25)
  L03_SIG w0.381: 60.99,2.1 J12.13 ; 59.72,2.1 J12.11
  L04_MIX w0.381: 59.72,2.1 J12.11 ; 60.99,2.1 J12.13
  BOTTOM w0.381: D4.A 69.57,29.49 69.57,34.1 67.07,36.6 61.29,36.6 60.83,37.06 60.83,38.68 59.83,39.68 59.83,42.62 59.34,43.11 59.34,44.28 56.57,47.06 55.37,47.06 v1(54.18,48.25)
  vias: v1(66.19,1.82) v1(66.29,3.7) v1(67.44,2.71) v1(68.43,27.5) v1(69.06,27.25) v1(69.75,27.3)
VTARG_MEAS: length 6.1
  TOP w0.114: U2.32 38.24,39.15 37.54,39.85 v1(37.03,39.85)
  BOTTOM w0.114: R136.2 37.57,38.95 37.57,39.32 v1(37.03,39.85) 37.68,40.5 R130.2
VTARG_MON: length 26.9
  L06_SIG w0.114: v1(36.91,42.79) 39.04,42.79 39.4,43.15 47.25,43.15 49.87,40.53 v1(50.19,40.53)
  BOTTOM w0.114: R130.1 36.64,42.53 v1(36.91,42.79) 36.64,43.06 R123.2 ; U26.1 47.71,33.06 47.32,33.44 47.32,37.48 50.19,40.35 v1(50.19,40.53)
VTARG_REF: length 4.3
  BOTTOM w0.381: 72.98,3.48 J11.1 73.76,2.1 ; 53.37,2.1 J12.1 52.58,3.48
WL_GPIO_1: length 20.1
  TOP w0.114: R20.1 124.45,48.44 v1(124.43,48.46) 124.36,48.46 123.7,49.12 123.7,49.53 124.47,50.31 U6.18
  L03_SIG w0.114: TP16.1 132.31,44.9 126.85,44.9 126.21,45.53 126.21,48.86 125.47,49.6 125.07,49.6 124.64,49.17 124.64,48.67 v1(124.43,48.46)
WL_GPIO_2: length 18.4
  TOP w0.114: U6.17 124.02,50.2 123.32,49.5 v1(123.32,48.79)
  L03_SIG w0.114: TP11.1 133.83,45.15 127.1,45.15 126.47,45.79 126.47,48.96 125.58,49.85 123.93,49.85 123.32,49.24 v1(123.32,48.79)
WL_GPIO_4: length 20.5
  TOP w0.114: v1(123.39,47.26) 122.9,47.75 122.9,48.2 122.61,48.49 122.61,48.51 122.58,48.54 122.58,49.83 123.22,50.46 123.22,50.87 123.12,50.96 U6.15
  L03_SIG w0.114: TP19.1 126.59,40.45 124.46,42.59 124.46,46.19 v1(123.39,47.26)
WL_HOST_WAKE_P2_7: length 63.4
  TOP w0.114: U1.N4 78.13,42.44 v1(77.83,42.74) ; U6.27 v1(125.17,54.3)
  L03_SIG w0.114: v1(112.75,48.61) 115.12,48.61 116.5,47.23 116.75,47.23 119.42,44.56 120.11,44.56 120.68,45.13 120.68,45.56 121.54,46.42 121.54,48.61 124.24,51.31 124.65,51.31 125.27,51.94 125.27,54.2 v1(125.17,54.3)
  L06_SIG w0.114: v1(77.83,42.74) 77.83,43.5 80.49,46.17 87.66,46.17 88.01,46.53 89.89,46.53 90.66,47.29 94.69,47.29 95.3,46.69 109.89,46.69 111.91,48.71 112.65,48.71 v1(112.75,48.61)
  BOTTOM w0.114: R133.2 76.94,42.49 77.19,42.74 v1(77.83,42.74)
WL_JTAG_TCK: length 12.2
  BOTTOM w0.114: R113.2 124.21,43.88 124.51,43.58 126.16,43.58 127.43,42.31 127.43,38.27 128.73,36.97 J25.9
WL_JTAG_TDI: length 6.8
  BOTTOM w0.114: J25.3 131.17,40.78 131.29,40.91 131.29,43.65 130.17,44.78 R116.2
WL_JTAG_TDO: length 13.1
  L03_SIG w0.114: v1(127.51,43.73) 127.61,43.63 130.91,43.63 132.05,42.49 v1(132.05,41.98)
  BOTTOM w0.114: R117.2 125.68,44.51 125.93,44.26 126.97,44.26 v1(127.51,43.73) ; v1(132.05,41.98) 131.55,41.47 131.55,39.76 131.31,39.51 J25.5
WL_JTAG_TMS: length 9.3
  BOTTOM w0.114: J25.7 128.73,38.24 127.71,39.26 127.71,42.49 127.53,42.68 127.53,43.06 128.22,43.75 128.22,44.45 R115.2
WL_JTAG_TRSTN: length 4.1
  BOTTOM w0.114: R114.2 128.68,44.49 129.9,43.27 129.9,42.33 J25.1
WL_REG_ON_P2_6: length 64.4
  TOP w0.114: U1.M4 v2(79.6,42.15) ; U6.28 v1(126.59,54.75)
  L03_SIG w0.114: v1(126.59,54.75) 125.55,53.71 125.55,51.86 121.87,48.18 121.87,44.75 v1(122.35,44.26)
  L06_SIG w0.114: v2(79.6,42.15) 79.93,41.82 80.38,41.82 80.47,41.73 81.72,41.73 82.97,42.98 88.58,42.98 89.1,43.5 100.71,43.5 101.79,44.58 111.86,44.58 113.49,46.2 114.12,46.2 116.5,48.58 119.1,48.58 120.27,47.41 120.27,46.38 120.6,46.05 120.6,44.57 120.9,44.26 v1(122.35,44.26)
  BOTTOM w0.114: v1(126.59,54.75) 126.54,54.7 126.54,53.62 R89.1
WL_VBAT: length 14.8
  TOP w0.254: U6.30 126.59,55.65
  TOP w0.305: 126.59,55.65 126.81,55.43
  TOP w0.381: 126.81,55.43 127.52,54.72 C11.1
  TOP w0.635: TP4.1 131.68,54.84 L3.2 ; 129.39,54.41 129.08,54.72 C11.1
  BOTTOM w0.508: TP4.1 131.68,60.14 131.1,60.71 C53.1 130.05,60.71 U11.1 U11.4
WL_VDDIO: length 42.5
  TOP w0.254: U6.36 124.47,57.74
  TOP w0.381: 124.47,57.74 124.47,58.92 C5.1
  TOP w0.508: TP1.1 C5.1
  TOP w0.635: v1(131.7,46.18) R25.1 R24.1 R23.1 R22.1 R21.1 124.46,46.18 R20.2
  L05_MIX w0.635: v1(120.52,57.83) 120.52,58.21 121.36,59.05 126.09,59.05 128.47,56.66 128.47,54.15 127.41,53.08 127.41,52.37 128.04,51.73 v1(130.76,51.73) 131.62,51.73 132.54,50.82 132.54,47.08 131.7,46.25 v1(131.7,46.18)
  BOTTOM w0.381: 123.71,60.52 TP1.1 ; TP1.1 124.57,61.39 ; TP1.1 124.57,59.65
  BOTTOM w0.508: R89.2 127.37,51.77 R96.1 130.72,51.77 v1(130.76,51.73)
XRES_L: length 90.1
  TOP w0.114: U1.F1 v2(84.07,44.67) ; v1(37.87,7.05) 37.33,6.51 SW1.B ; v1(75.03,11.75) 74.68,11.4 57.98,11.4 v1(57.35,10.77)
  L03_SIG w0.114: v1(37.95,11.33) 37.95,7.13 v1(37.87,7.05) ; v2(84.07,44.67) 83.9,44.67 83.57,44.35 83.29,44.35 83.03,44.09 83.03,42.53 80.38,39.88 79.25,39.88 78.44,39.06 75.16,39.06 74.9,38.8 74.9,38.17 75.79,37.28 75.79,32.05 v1(75.72,31.98) 75.72,31.64 75.84,31.52 75.84,19.28 75.03,18.47 v1(75.03,11.75)
  L06_SIG w0.114: v1(37.95,11.33) 40.87,11.33 41.84,10.36 52.43,10.36 53.7,11.63 56.5,11.63 v1(57.35,10.77)
  BOTTOM w0.114: v1(75.72,31.98) C121.1 76.59,31.59 R147.2 ; R190.1 v1(57.35,10.77)
N17133469: length 5.8
  TOP w0.114: v1(35.64,41) 36.2,40.44 37.59,40.44 38.64,39.39 U2.31
  BOTTOM w0.114: v1(35.64,41) 35.26,41.37 C97.1
N17133474: length 2.8
  TOP w0.114: v1(37.41,29.06) 37.84,29.48 U2.53
  BOTTOM w0.114: C130.1 37.03,28.68 v1(37.41,29.06)
N17133557: length 3.4
  TOP w0.203: U2.22 42.25,38.3 42.25,40.77 R35.2
N17133559: length 3.2
  TOP w0.203: R34.2 41.84,41.19 U2.23
N17715190: length 1.5
  BOTTOM w0.114: U30.14 33.31,21.59 R164.1
N17715216: length 1.5
  BOTTOM w0.114: C143.2 30.28,19.78 U30.3
N17715264: length 1.4
  BOTTOM w0.114: U30.2 30.78,19.69 R171.2
N17715329: length 2.1
  BOTTOM w0.254: U30.11 31.03,23.69 v1(31.19,23.85) v1(31.19,24.61)
  vias: v1(31.95,32.61) v1(31.95,27.91) v1(33.22,32.61) v1(33.22,27.91)
N17715335: length 2
  BOTTOM w0.254: v1(29.92,24.61) v1(29.92,23.85) 30.03,23.74 U30.9
  vias: v1(27.51,32.61) v1(27.51,27.91) v1(28.55,27.91) v1(28.78,32.61)
N17734371: length 5
  TOP w0.114: C28.1 15.2,43.98 R26.2 16.24,46.35 U3.31
N18060252: length 4.7
  BOTTOM w0.114: U30.5 28.82,21.09 28.14,20.42 R169.2 27.29,21.68 C142.2 26.03,21.71 R165.1
N18103700: length 2.9
  BOTTOM w0.114: U19.1 46.1,53.62 46.94,54.46 C67.1
N18103720: length 1.3
  TOP w0.254: v1(46.3,56.62) 46.3,56.24 C9.1
N18103734: length 3.1
  TOP w0.457: C9.2 46.94,53.44 v1(46.81,53.31)
  BOTTOM w0.305: U19.2 46.62,53.12 v1(46.81,53.31)
N18103773: length 3.9
  BOTTOM w0.114: U19.15 39.37,52.12 39.19,52.3 R92.1 R98.2
N18103970: length 1.6
  BOTTOM w0.114: R105.1 41.81,48.93 U19.12
N18115594: length 4.3
  TOP w0.114: U10.4 R50.1 67.76,28.9 R51.2 R46.2
N18115805: length 4.8
  TOP w0.114: R48.1 75.58,31.02 75.16,31.44 75.16,33.07 SW5.1
N18115822: length 3.1
  TOP w0.114: R51.1 69.73,28.36 70.85,27.24 SW5.3
N18115824: length 11.1
  TOP w0.114: SW5.4 75.16,25.07 v1(75.16,24.2)
  L06_SIG w0.114: v1(75.16,24.2) 75.16,24.79 74.56,25.39 68.89,25.39 v1(68.4,25.88)
  BOTTOM w0.114: U27.7 68.24,25.73 v1(68.4,25.88)
N18116972: length 26.7
  TOP w0.114: v1(36.42,49.85) 34.21,49.85 28.12,55.95 27.46,55.95 24.76,58.65 15.63,58.65 14.89,57.91 LED6.K
  BOTTOM w0.114: R102.2 36.52,49.76 v1(36.42,49.85)
N18117036: length 12.9
  TOP w0.114: R57.2 26.2,22.86 22.78,19.45 22.78,17.49 21.35,16.05 LED4.A
N18205136: length 4
  BOTTOM w0.114: R137.2 23.83,36.46 R140.2 ; R140.2 23.83,36.39 R144.1 ; R140.2 22.44,36.42 R139.1
N18205137: length 2.3
  BOTTOM w0.114: Q1.4 20.25,35.17 R143.2
N18205190: length 2.4
  BOTTOM w0.114: R138.2 20.02,37.71 Q1.2
N18323163: length 2.3
  BOTTOM w0.114: R185.2 7.57,10.13 8.5,11.07 U31.5
N18323191: length 2.2
  BOTTOM w0.114: C146.2 9.5,10.24 U31.3
N18323726: length 3.7
  BOTTOM w0.381: 4.06,64.68 J16.2 ; J16.2 5.3,65.91 ; J16.2 2.83,65.91
N18429699: length 3.2
  BOTTOM w0.114: R104.2 R100.1 55.45,50.77 55.96,51.29 U17.11
N18439299: length 2.9
  TOP w0.203: U1.J2 v2(81.55,44.02)
  BOTTOM w0.254: L9.1 81.77,46.04 81.77,44.24 v2(81.55,44.02)
N18439327: length 3.1
  TOP w0.203: U1.K2 v2(80.9,44.02)
  BOTTOM w0.254: L9.2 80.05,46 80.64,45.41 80.64,44.28 v2(80.9,44.02)
N18453045: length 5.5
  BOTTOM w0.152: R97.2 77.45,51.17 C75.1 77.45,53.78 77.24,53.98 U15.4 74.74,53.98 U14.4
N18482506: length 67.7
  TOP w0.114: R32.2 74.07,43.31 73.72,43.31 73.2,43.84 v1(73.2,45.03) ; R25.2 130.68,47.95 v1(130.17,48.46)
  L06_SIG w0.114: v1(130.17,48.46) 129.4,49.23 126.21,49.23 125.63,49.81 125.11,49.81 121.64,53.29 115.7,53.29 114.91,52.5 108.57,52.5 107.03,50.96 99.2,50.96 98.52,50.28 94.86,50.28 94.56,49.98 88.11,49.98 86.33,48.2 79.1,48.2 76.93,46.04 76.88,46 76.82,45.98 76.76,45.97 74.13,45.97 v1(73.2,45.03)
  BOTTOM w0.114: R111.1 v1(130.17,48.46)
N18482508: length 68
  TOP w0.114: v1(128.68,48.46) 129.43,47.71 R24.2
  L06_SIG w0.114: v1(73.75,41.47) 74.9,41.47 80.06,46.63 87.3,46.63 87.73,47.06 89.51,47.06 90.27,47.82 95.1,47.82 95.73,47.19 109.63,47.19 111.84,49.4 114.73,49.4 116.76,51.44 119.32,51.44 121.56,49.19 121.56,47.18 122.57,46.17 127.84,46.17 128.68,47.01 v1(128.68,48.46)
  BOTTOM w0.114: R132.2 v1(73.75,41.47) ; R109.1 v1(128.68,48.46)
N18482512: length 61.6
  TOP w0.114: R22.2 126.94,47.27 125.81,48.4 v1(125.68,48.4)
  L06_SIG w0.114: v1(73.79,42.74) 75.79,42.74 79.91,46.86 79.97,46.86 79.97,46.86 87.15,46.86 87.6,47.31 89.38,47.31 90.14,48.07 95.22,48.07 95.86,47.44 109.5,47.44 111.72,49.66 114.63,49.66 116.66,51.69 119.55,51.69 121.59,49.65 123.14,49.65 123.93,48.86 123.93,48.23 124.21,47.95 125.23,47.95 v1(125.68,48.4)
  BOTTOM w0.114: R128.2 v1(73.79,42.74) ; R112.1 v1(125.68,48.4)
N18482514: length 72.5
  TOP w0.114: R36.2 v1(74.64,40.57)
  L06_SIG w0.114: v1(74.64,40.57) 74.64,40.72 80.32,46.4 87.5,46.4 87.91,46.8 89.71,46.8 90.45,47.54 94.87,47.54 95.47,46.94 109.74,46.94 111.94,49.14 114.83,49.14 116.84,51.15 119.13,51.15 121.31,48.96 121.31,47.01 122.66,45.66 128.78,45.66 131.62,48.51 131.62,50.08 v1(131.32,50.39)
  BOTTOM w0.114: R99.1 129.58,50.72 R96.2 130.95,50.73 131.29,50.39 v1(131.32,50.39)
N18482516: length 61.8
  TOP w0.114: R28.2 v1(73.76,44.01) ; v1(124.18,49.34) 124.31,49.22 124.43,49.22 125.19,48.46 125.19,47.73 R21.2
  L06_SIG w0.114: v1(124.18,49.34) 123.29,50.23 122.4,50.23 122,50.64 122,51.38 120.85,52.52 116.56,52.52 114.27,50.23 111.15,50.23 109.88,48.96 107.67,48.96 107.04,48.33 95.99,48.33 95.35,48.96 90.04,48.96 89.28,48.2 87.35,48.2 86.72,47.57 79.73,47.57 76.17,44.01 v1(73.76,44.01)
  BOTTOM w0.114: v1(124.18,49.34) 123.97,49.14 123.97,47.9 124.21,47.67 R108.1
N18482684: length 61.4
  TOP w0.114: R23.2 127.84,47.57 127.84,47.78 v1(127.18,48.43)
  L06_SIG w0.114: v1(127.18,48.43) 126.64,48.43 125.52,49.55 125.01,49.55 121.53,53.04 115.99,53.04 115.17,52.22 108.67,52.22 107.09,50.64 99.46,50.64 98.82,50 95,50 94.7,49.71 88.24,49.71 86.45,47.92 79.25,47.92 77.01,45.69 75.15,45.69 v1(74.48,45.01)
  BOTTOM w0.114: v1(74.48,45.01) 74.64,44.85 R122.2 ; R110.1 v1(127.18,48.43)
N18528852: length 2.6
  TOP w0.254: U6.34 125.37,57.73 125.63,57.98
  TOP w0.635: 125.63,57.98 126.41,58.76 L2.1
N18619822: length 6.1
  TOP w0.559: C4.1 122.24,61.25 L12.1 122.24,62.55 arc(122.87,64.07) C2.2 125.8,64.7 L1.2
N18697642: length 7
  TOP w0.114: LED7.A v1(15.95,59.92)
  BOTTOM w0.114: v1(15.95,59.92) 16.33,60.3 R75.2
N18699542: length 10.1
  TOP w0.114: LED1.A 21.19,18.23 21.69,18.74 21.69,19.42 24.98,22.71 R56.2
N18699562: length 4.3
  TOP w0.114: LED2.A 20.38,22.82 22.54,24.98 R54.2
N18699568: length 7.2
  TOP w0.114: R55.2 23.76,23.42 20.75,20.41 LED3.A
N18713395: length 3.8
  TOP w0.114: U8.3 51.25,33.25 51.41,33.09 51.41,31.58 C44.2 50.78,30.92 R49.2
N18743253: length 4.8
  BOTTOM w0.114: U30.1 31.28,20.37 31.48,20.17 32.77,20.17 33.03,20.42 R168.2 34.11,21.15 R163.1
N18777793: length 4.4
  BOTTOM w0.114: C91.1 45.19,44.68 45.08,44.56 U23.4 ; C91.1 46.04,45.94 R118.2 ; C91.1 46.05,44.67 R125.2
N18781968: length 3.9
  BOTTOM w0.114: U17.2 58.27,55.95 58.39,56.08 58.39,57.23 R77.2
N18781971: length 3.4
  BOTTOM w0.114: R81.2 58.9,56.84 58.78,56.71 58.78,55.69 58.53,55.45 U17.3
N18781974: length 2.3
  BOTTOM w0.114: U17.4 59.42,54.95 R85.2
N18782191: length 2.4
  BOTTOM w0.114: U17.6 58.36,53.95 58.78,53.54 R88.2
N18782194: length 3.4
  BOTTOM w0.114: R93.2 59.78,52.27 59.28,52.27 58.1,53.45 U17.7
N18810466: length 12.8
  L06_SIG w0.381: J8.1 55.35,32.43 ; J8.1 56.43,31.35 ; J8.1 54.26,31.35 ; J8.1 55.35,30.27
  BOTTOM w0.203: U25.5 50.98,33.86 51.38,33.86 U25.4 51.38,31.93 51.38,31.89 51.38,31.85 R148.1
  BOTTOM w0.381: J8.1 56.43,31.35 ; J8.1 54.26,31.35 ; J8.1 55.35,30.27 ; R148.1 50.74,31.6 50.41,31.93 v1(50.41,32.51) v1(49.73,32.51)
N18832502: length 20.9
  TOP w0.114: v1(112.23,51.11) R12.2 112.23,50.02 LED5.2 ; LED9.A LED8.A 120.07,41.01 118.85,42.23 v1(118.85,43.12)
  L03_SIG w0.114: v1(112.23,51.11) 111.54,50.42 111.54,47.76 111.73,47.57 114.53,47.57 118.85,43.25 v1(118.85,43.12)
N18832516: length 1.5
  TOP w0.114: LED8.K 120.24,44.4 R27.2
N18832538: length 1.7
  TOP w0.114: LED9.K 123.75,43.21 R31.2
N18832599: length 1.8
  TOP w0.114: LED5.4 117.54,47.22 R19.1
N18832601: length 1.6
  TOP w0.114: LED5.3 115.66,50.09 R8.1
N18832603: length 1.9
  TOP w0.114: R18.2 112.36,47.22 LED5.1
N18833732: length 13.2
  TOP w0.114: v1(12.12,7.36) 12.12,5.5 11.18,4.57 SW2.A
  BOTTOM w0.114: v1(12.12,7.36) 14.83,10.08 R66.2 16.54,11.15 R65.1
N18852351: length 4.2
  TOP w0.254: 127.53,56.2 127.44,56.1 125.83,56.1 U6.31
  TOP w0.508: 127.53,56.2 128.63,56.2 129.41,56.99 129.41,57.2 C7.1
N18920306: length 2.8
  TOP w0.381: R42.2 R41.1 U9.4
N18985234: length 2
  BOTTOM w0.203: J28.B5 106.86,66.52 R199.2
N18985239: length 3.4
  TOP w0.203: R198.2 109.32,63.16 109.12,63.16 108.4,63.88 J28.A5
N19031222: length 6.3
  TOP w0.559: ANT1.1 132.01,66.31 arc(130.23,65.13) C1.2 128.11,64.69 L1.1
N19038486: length 2
  TOP w0.559: L13.1 125.81,67.68 J29.I

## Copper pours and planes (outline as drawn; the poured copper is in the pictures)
5V_OUT on BOTTOM: 29.54,21.95 29.54,24.74 29.41,24.87 28.52,24.87 28.02,25.37 17.35,25.37 17.35,23.39 18.39,22.34 18.39,19.55 18.85,19.09 24.31,19.09 24.71,19.5 24.71,22.2 24.84,22.33 27.89,22.33 28.27,21.95
5V_OUT on L05_MIX: 48.36,22.42 48.72,22.78 48.72,24.25 46.23,26.74 27.66,26.74 26.52,25.6 26.52,22.8 26.9,22.42
GND on BOTTOM (solid shape): 30.66,23.27 30.66,21.69 31.22,21.69 31.32,21.59 31.32,21.31 31.19,21.18 29.92,21.18 29.79,21.31 29.79,21.62 29.87,21.69 30.4,21.69 30.4,23.29 30.63,23.29
GND on TOP: 1.97,1.02 1.02,1.97 1.02,69.16 2.06,70.21 135.84,70.21 135.84,32.33 98.04,32.33 97.99,32.28 97.99,1.02 92.84,1.02 92.84,13.58 87.12,19.3 87.12,30.09 86.62,30.58 84.74,30.58 84.24,30.08 84.24,17.31 87.17,14.38 87.17,11.79 87.98,10.98 87.98,1.09 87.9,1.02 ; 80 cut-outs
GND on TOP: 128.14,56.43 128.14,57.68 128.04,57.78 125.83,57.78 125.78,57.73 125.78,56.89 125.58,56.69 125.58,56.51 125.65,56.43
GND on BOTTOM: 1.02,1.97 1.02,69.16 2.06,70.21 135.84,70.21 135.84,32.33 98.07,32.33 97.99,32.26 97.99,1.02 92.84,1.02 92.84,13.58 87.12,19.3 87.12,30.09 86.62,30.58 84.74,30.58 84.24,30.08 84.24,17.31 87.17,14.38 87.17,11.79 87.98,10.98 87.98,1.09 87.9,1.02 1.97,1.02 ; 97 cut-outs
GND on L02_GND: 1.02,1.97 1.02,69.16 2.06,70.21 135.84,70.21 135.84,1.02 92.84,1.02 92.84,13.58 87.12,19.3 87.12,30.09 86.62,30.58 84.74,30.58 84.24,30.08 84.24,17.31 87.17,14.38 87.17,11.79 87.98,10.98 87.98,1.09 87.9,1.02 1.97,1.02 ; 1 cut-out
GND on L03_SIG: 1.02,1.97 1.02,69.16 2.06,70.21 135.84,70.21 135.84,1.02 92.84,1.02 92.84,13.58 87.12,19.3 87.12,30.09 86.62,30.58 84.74,30.58 84.24,30.08 84.24,17.31 87.17,14.38 87.17,11.79 87.98,10.98 87.98,1.09 87.9,1.02 1.97,1.02 ; 34 cut-outs
GND on L04_MIX: 132.23,41.98 132.23,52.57 132.94,53.28 135.48,53.28 135.86,53.66 135.86,65.37 131.29,69.94 131.27,69.94 131.04,70.17 96.77,70.17 96.09,69.49 96.09,63.16 96.29,62.96 98.04,62.96 101.7,66.62 109.42,66.62 109.7,66.34 109.7,63.52 108.69,62.5 103.68,62.5 101.45,60.27 101.45,55.57 101.96,55.06 107.04,55.06 107.42,54.68 107.42,40.71 107.8,40.33 130.58,40.33
GND on L04_MIX: 1.02,1.97 1.02,69.16 2.06,70.21 95.06,70.21 95.48,69.79 95.48,60.9 96.62,59.76 100.81,59.76 101.07,59.5 101.07,55.44 101.83,54.68 106.65,54.68 107.04,54.3 107.04,40.58 107.67,39.95 130.53,39.95 132.56,41.98 132.56,52.52 132.94,52.9 135.46,52.9 135.84,52.52 135.84,2.74 134.12,1.02 92.84,1.02 92.84,13.58 87.12,19.3 87.12,30.09 86.62,30.58 84.74,30.58 84.24,30.08 84.24,17.31 87.17,14.38 87.17,11.79 87.98,10.98 87.98,1.09 87.9,1.02 1.97,1.02
GND on L05_MIX: 114.73,60.55 114.73,44.67 106.76,44.67 93.14,31.06 87.1,31.06 87.1,19.3 92.84,13.56 92.84,1.08 98.09,1.08 98.09,32 98.27,32.17 135.23,32.17 135.76,32.71 135.76,70.12 108.94,70.12 107.85,69.03 107.85,61.82 108.74,60.93 114.35,60.93
GND on L05_MIX: 97.26,57.6 98.53,58.87 98.53,62.55 98.15,62.93 84.68,62.93 84.3,62.55 84.3,58.62 85.32,57.6
GND on L05_MIX: 50.9,39.41 50.9,35.63 50.65,35.37 48.23,35.37 47.98,35.63 47.98,37.03 48.49,37.53 48.49,39.46 48.95,39.92 50.39,39.92
GND on L06_SIG: 1.97,1.02 1.02,1.97 1.02,69.21 2.01,70.21 135.84,70.21 135.84,1.02 92.84,1.02 92.84,13.58 92.3,14.12 92.3,30.29 93.57,31.56 93.57,35.63 91.29,37.91 81.89,37.91 80.87,36.9 80.87,32.45 83.54,29.79 83.54,17.98 87.17,14.35 87.17,11.79 87.98,10.98 87.98,1.09 87.9,1.02 ; 35 cut-outs
GND on L07_GND: 1.02,1.97 1.02,69.21 2.01,70.21 135.84,70.21 135.84,32.11 98.37,32.11 98.25,31.98 98.25,1.02 92.84,1.02 92.84,13.58 87.12,19.3 87.12,30.09 86.63,30.58 84.74,30.58 84.24,30.08 84.24,17.31 87.17,14.38 87.17,11.79 87.98,10.98 87.98,1.09 87.9,1.02 1.97,1.02
GND_EARTH1 on BOTTOM: 115.77,65.66 111.29,65.66 111.29,66.78 111.03,67.03 104.3,67.03 104.18,66.9 104.18,65.66 102.16,65.66 101.46,64.96 100.69,64.96 100.51,65.14 100.51,69.11 101.6,70.21 113.03,70.21 113.24,69.99 115.67,69.99 115.77,69.89
GND_EARTH2 on BOTTOM: 97.38,62.31 97.38,59.73 97.01,59.36 92.08,59.36 91.11,60.33 87.43,60.33 86.46,59.36 85.22,59.36 83.95,58.09 81.41,58.09 80.37,59.13 80.37,62.63 81.18,63.45 95.55,63.45 95.99,63.02 96.67,63.02
GND_EARTH3 on TOP: 1.09,46.7 1.09,57.51 1.47,57.89 5.92,57.89 6.05,57.76 6.05,46.96 5.45,46.37 1.42,46.37 ; 2 cut-outs
GND_EARTH3 on BOTTOM: 8.64,44.81 1.6,44.81 1.09,45.31 1.09,57.51 1.47,57.89 5.92,57.89 6.05,57.76 6.05,55.34 4.39,55.34 4.14,55.08 4.14,49.5 4.42,49.22 6.02,49.22 6.05,49.19 6.05,46.96 6.18,46.83 8.46,46.83 8.84,46.45 8.84,45
VBAT on L06_SIG: 44.45,48.2 40.61,48.2 40.11,47.69 40.11,46.8 39.73,46.42 28.8,46.42 26.9,48.33 22.58,48.33 21.82,47.57 15.98,47.57 11.02,52.52 11.02,52.53 10.41,53.14 10.41,58.09 11.02,58.7 11.02,60.39 10.26,61.16 10.26,66.31 10.64,66.69 14.81,66.69 15.21,66.29 15.21,55.69 16.1,54.81 20.42,54.81 22.07,53.15 23.47,53.15 24.74,51.88 29.06,51.88 29.95,51 36.68,51 36.93,51.25 41.91,51.25 42.51,50.65 44.04,50.65 44.81,49.88 44.81,48.56
VBAT_PP on TOP: 40.36,57.19 40.36,56.1 41.27,55.19 42.52,55.19 42.52,57.07 42.24,57.35 40.51,57.35
VBAT_PP on BOTTOM: 44.15,51.28 44.15,48.36 45.93,48.36 46.18,48.61 46.18,50.7 45.59,51.28
VBAT_PP on BOTTOM: 40.34,56.79 40.34,57.62 38.38,59.58 38.38,61.41 38.67,61.7 41.72,61.7 42.3,61.12 42.3,56.8 42.11,56.61 40.51,56.61
VBAT_PP on L03_SIG: 38.96,57.85 38.96,50.57 39.98,49.55 45.8,49.55 46.08,49.83 46.08,55.58 45.79,55.86 45.79,57.76 45.19,58.36 39.47,58.36
VBUS_DEV on BOTTOM: 93.99,47.22 93.99,51.38 91.92,51.38 91.92,47.22
VBUS_DEV on BOTTOM: 104.33,64.78 105.79,66.24 106.53,66.24 106.78,65.98 106.78,62.91 106.68,62.81 104.75,62.81 104.39,62.45 102.16,62.45 101.41,61.7 101.41,60.65 101.16,60.4 98.52,60.4 98.37,60.55 98.37,62.48 100.67,64.78
VBUS_DEV on L03_SIG: 104.39,63.26 104.39,64.36 105.18,65.14 105.18,65.74 105.71,66.27 109.37,66.27 109.89,65.75 109.89,64.17 109.75,64.03 108.03,64.03 107.19,63.19 104.47,63.19
VBUS_DEV on L04_MIX: 98.83,62.93 98.83,61.08 99.59,60.32 101.04,60.32 103.58,62.86 106.96,62.86 107,62.9 107.76,62.9 109.22,64.36 109.22,66.06 109.07,66.21 102.11,66.21
